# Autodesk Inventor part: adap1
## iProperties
Created: 2006-11
Part Number: adap1
Material: Steel
Document SubType Name: Sheet Metal
Designer: WINDGES
Author: WINDGES
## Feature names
1. Bohrung1 [Hole]
2. Rechteckige Anordnung1 [Rectangular Pattern]
3. Grobblech1
4. Biegung1
